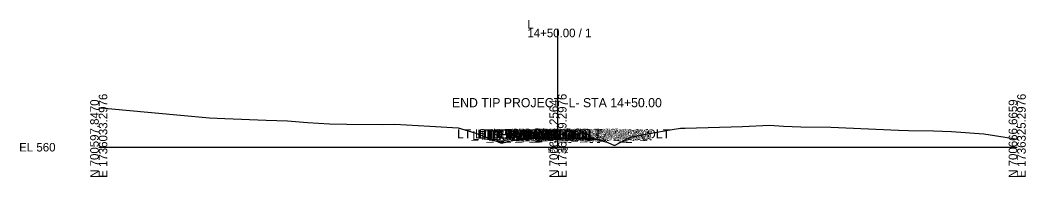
# Model space of a CAD drawing. Extents: x -26 to 697, y -10 to 2642.
# Drawn here: x -25.7 to 302.8, y 2590.3 to 2641.5 of the extents above; entities that cross this region are included whole.
import ezdxf

# ---------------------------------------------------------------- set-up
doc = ezdxf.new("R2010")
doc.units = 0
for name, color, linetype in [('Default', 7, 'Continuous'), ('Exist CMT Pavement', 7, 'Continuous'), ('Exist Cross Section Cell', 7, 'Continuous'), ('Exist XS Center Line Elevation Label', 7, 'Continuous'), ('Exist XS Ground Line', 7, 'Continuous'), ('Prop CMT Pvmt Course 1', 7, 'Continuous'), ('Prop CMT Pvmt Course 1 Wedge', 7, 'Continuous'), ('Prop CMT Pvmt Course 2', 7, 'Continuous'), ('Prop CMT Pvmt Course 2 Wedge', 7, 'Continuous'), ('Prop CMT Pvmt Surface', 7, 'Continuous'), ('Prop CMT Pvmt Surface Shoulder', 7, 'Continuous'), ('Prop CMT Pvmt Wedge Surface 1', 7, 'Continuous'), ('Prop CMT Pvmt Wedge Surface 2', 7, 'Continuous'), ('Prop CMT Shld Paved Course 1', 7, 'Continuous'), ('Prop CMT Shld Paved Course 2', 7, 'Continuous'), ('Prop CMT Slope Grass', 7, 'Continuous'), ('Prop CMT Subgrade Earthwork', 7, 'Continuous'), ('Prop XS SE Text', 7, 'Continuous'), ('Prop XS Side Slope Text', 7, 'Continuous')]:
    doc.layers.add(name, color=color, linetype=linetype)

msp = doc.modelspace()

# ---------------------------------------------------------------- linework, layer by layer
at = {"layer": 'Exist CMT Pavement'}
for points in [[(150, 2603.02), (140.36, 2602.87)], [(140.36, 2602.87), (145.18, 2602.94)], [(145.18, 2602.94), (150, 2603.02)], [(154.82, 2602.95), (150, 2603.02)], [(150, 2603.02), (159.65, 2602.87)], [(159.65, 2602.87), (154.82, 2602.95)]]:
    msp.add_lwpolyline(points, dxfattribs=at)
at = {"layer": 'Exist Cross Section Cell'}
for p, q in [((150, 2600), (150, 2638.72)), ((0, 2600), (150, 2600)), ((150, 2600), (300, 2600))]:
    msp.add_line(p, q, dxfattribs=at)
at = {"layer": 'Exist XS Ground Line'}
msp.add_lwpolyline([(0, 2612.91), (0.83, 2612.84), (8.98, 2612.08), (26.7, 2610.49), (36.16, 2609.64), (41.19, 2609.42), (54.71, 2608.85), (61.69, 2608.57), (68.16, 2608.12), (75.34, 2607.6), (81.04, 2607.57), (92.53, 2607.38), (96.74, 2607.49), (108.14, 2606.89), (117.37, 2606.36), (122.81, 2604.68), (131.51, 2601.35), (136.08, 2602.43), (140.32, 2602.87), (147.42, 2602.97), (149.92, 2603.02), (152.45, 2602.99), (159.65, 2602.87), (160.58, 2602.74), (163.68, 2602.33), (166.32, 2601.5), (168.44, 2600.51), (171.97, 2602.4), (173.71, 2603.3), (179.74, 2604.43), (187.34, 2605.75), (189.97, 2606.2), (191.5, 2606.25), (210.28, 2606.73), (219.14, 2607.15), (223.68, 2606.87), (229.3, 2606.65), (239.08, 2606.6), (261.25, 2605.54), (264.53, 2605.47), (272.61, 2605.38), (278.5, 2605.11), (289.13, 2604.41), (296.1, 2603.33), (300, 2602.59)], dxfattribs=at)
at = {"layer": 'Prop CMT Pvmt Course 1'}
for points in [[(150, 2603.12), (140.36, 2602.99)], [(140.36, 2602.88), (150, 2603.02)], [(140.36, 2602.99), (140.36, 2602.78), (140.36, 2602.78), (140.36, 2602.88)], [(150, 2602.92), (150, 2603.12)], [(150, 2603.12), (159.65, 2602.96)], [(150, 2602.92), (150, 2603.12)], [(150, 2603.02), (150, 2602.92), (150, 2602.92)], [(159.65, 2602.86), (150, 2603.02)], [(150, 2603.02), (150, 2602.92), (150, 2602.92)], [(159.65, 2602.96), (159.65, 2602.75)], [(159.65, 2602.75), (159.65, 2602.86)], [(159.65, 2602.75), (159.65, 2602.75)]]:
    msp.add_lwpolyline(points, dxfattribs=at)
at = {"layer": 'Prop CMT Pvmt Course 1 Wedge'}
for points in [[(150, 2603.02), (140.36, 2602.88)], [(150, 2603.02), (159.65, 2602.86)]]:
    msp.add_lwpolyline(points, dxfattribs=at)
at = {"layer": 'Prop CMT Pvmt Course 2'}
for points in [[(140.36, 2602.32), (140.36, 2602.32), (140.36, 2602.78), (140.36, 2602.78)], [(140.36, 2602.78), (140.36, 2602.32)], [(159.65, 2602.29), (159.65, 2602.75)], [(159.65, 2602.75), (159.65, 2602.75)], [(159.65, 2602.75), (159.65, 2602.29)], [(159.65, 2602.29), (159.65, 2602.29)]]:
    msp.add_lwpolyline(points, dxfattribs=at)
at = {"layer": 'Prop CMT Pvmt Course 2 Wedge'}
for points in [[(150, 2602.92), (140.36, 2602.78)], [(150, 2602.92), (159.65, 2602.75)]]:
    msp.add_lwpolyline(points, dxfattribs=at)
at = {"layer": 'Prop CMT Pvmt Surface'}
for points in [[(150, 2603.12), (140.36, 2602.99)], [(150, 2603.12), (159.65, 2602.96)]]:
    msp.add_lwpolyline(points, dxfattribs=at)
at = {"layer": 'Prop CMT Pvmt Surface Shoulder'}
for points in [[(140.36, 2602.99), (140.35, 2602.99)], [(159.65, 2602.96), (159.66, 2602.96)]]:
    msp.add_lwpolyline(points, dxfattribs=at)
at = {"layer": 'Prop CMT Pvmt Wedge Surface 1'}
for points in [[(150, 2603.02), (140.36, 2602.88)], [(140.36, 2602.78), (140.36, 2602.99)], [(140.36, 2602.88), (140.36, 2602.78), (140.36, 2602.78)], [(150, 2603.12), (150, 2602.92), (150, 2602.92), (150, 2603.02)], [(150, 2603.12), (150, 2602.92), (150, 2602.92), (150, 2603.02)], [(150, 2603.02), (159.65, 2602.86)], [(159.65, 2602.75), (159.65, 2602.96)], [(159.65, 2602.86), (159.65, 2602.75)], [(159.65, 2602.75), (159.65, 2602.75)]]:
    msp.add_lwpolyline(points, dxfattribs=at)
at = {"layer": 'Prop CMT Pvmt Wedge Surface 2'}
for points in [[(140.36, 2602.78), (140.36, 2602.99)], [(150, 2602.92), (140.36, 2602.78)], [(150, 2603.12), (150, 2602.92)], [(150, 2603.12), (150, 2602.92)], [(150, 2602.92), (159.65, 2602.75)], [(159.65, 2602.75), (159.65, 2602.96)]]:
    msp.add_lwpolyline(points, dxfattribs=at)
at = {"layer": 'Prop CMT Shld Paved Course 1'}
for points in [[(140.36, 2602.99), (140.35, 2602.99), (140.14, 2602.77)], [(140.14, 2602.77), (140.36, 2602.78)], [(140.36, 2602.78), (140.36, 2602.99)], [(159.65, 2602.96), (159.66, 2602.96), (159.87, 2602.75)], [(159.65, 2602.75), (159.65, 2602.96)], [(159.87, 2602.75), (159.65, 2602.75)]]:
    msp.add_lwpolyline(points, dxfattribs=at)
at = {"layer": 'Prop CMT Shld Paved Course 2'}
for points in [[(140.36, 2602.78), (140.14, 2602.77), (140.13, 2602.77), (139.66, 2602.31)], [(139.66, 2602.31), (140.36, 2602.32)], [(140.36, 2602.32), (140.36, 2602.78)], [(159.65, 2602.75), (159.87, 2602.75), (159.88, 2602.75), (160.35, 2602.28)], [(159.65, 2602.29), (159.65, 2602.75)], [(160.35, 2602.28), (159.65, 2602.29)]]:
    msp.add_lwpolyline(points, dxfattribs=at)
at = {"layer": 'Prop CMT Slope Grass'}
for points in [[(140.35, 2602.99), (137.27, 2602.76), (136.74, 2602.49)], [(159.66, 2602.96), (162.72, 2602.72), (163.45, 2602.36)]]:
    msp.add_lwpolyline(points, dxfattribs=at)
at = {"layer": 'Prop CMT Subgrade Earthwork'}
for points in [[(139.66, 2602.31), (139.08, 2602.89)], [(140.36, 2602.32), (139.66, 2602.31)], [(140.36, 2602.32), (140.37, 2602.87)], [(140.36, 2602.32), (140.36, 2602.32)], [(159.65, 2602.29), (159.63, 2602.87)], [(159.65, 2602.29), (159.65, 2602.29)], [(159.65, 2602.29), (160.35, 2602.28)], [(160.35, 2602.28), (160.93, 2602.86)]]:
    msp.add_lwpolyline(points, dxfattribs=at)

# ---------------------------------------------------------------- texts
at = {"layer": 'Default'}
for s, height, p in [('LT_Sub_Trench_Out_DLT', 3, (117.03, 2602.89)), ('LT_Sub_Trench_Out', 3, (121.99, 2602.31)), ('LT_PV_Sub_Tie_Out', 3, (122.87, 2602.87)), ('LT_GS_OS_CTL', 3, (123.67, 2602.76)), ('LT_PS2_Shelf_Out', 3, (124.1, 2602.77)), ('LT_PV_OEEOP_EG', 3, (124.15, 2602.87)), ('LT_Slope_Fill', 3, (125.46, 2602.49)), ('LT_PV2_OEEOP', 3, (126.54, 2602.78)), ('LT_Sub_OEEOP', 3, (126.61, 2602.32)), ('LT_PV1_OEEOP', 3, (126.9, 2602.88)), ('LT_PS2_OEOP', 3, (127.5, 2602.77)), ('LT_PV2_OEOT', 3, (127.6, 2602.78)), ('LT_Sub_OEOT', 3, (127.67, 2602.32)), ('LT_PV1_OEOT', 3, (127.96, 2602.99)), ('LT_PS1_OEOP', 3, (128.07, 2602.99)), ('LT_PV_EG_TestPt', 3, (130.3, 2602.94)), ('RT_PV_IEEOP_EG', 3, (134.76, 2603.02)), ('LT_PV_IEEOP_EG', 3, (134.93, 2603.02)), ('RT_PV2_IEEOP', 3, (137.14, 2602.92)), ('LT_PV2_IEEOP', 3, (137.32, 2602.92)), ('RT_PV1_IEEOP', 3, (137.5, 2603.02)), ('LT_PV1_IEEOP', 3, (137.68, 2603.02)), ('RT_Sub_Trench_Out_DLT', 3, (138.7, 2602.86)), ('RT_PV_EG_TestPt', 3, (139.77, 2602.95)), ('RT_PV_Sub_Tie_Out', 3, (141.95, 2602.87)), ('PV2_PGL', 3, (142.05, 2602.92)), ('PV1_PGL', 3, (142.41, 2603.12)), ('RT_Sub_Trench_Out', 3, (142.5, 2602.28)), ('RT_PV_OEEOP_EG', 3, (143.26, 2602.87)), ('RT_PS2_Shelf_Out', 3, (143.67, 2602.75)), ('RT_PV2_OEEOP', 3, (145.65, 2602.75)), ('RT_Sub_OEEOP', 3, (145.72, 2602.29)), ('RT_PV1_OEEOP', 3, (146.01, 2602.86)), ('RT_PV2_OEOT', 3, (146.71, 2602.75)), ('RT_Sub_OEOT', 3, (146.78, 2602.29)), ('RT_PS2_OEOP', 3, (147.05, 2602.75)), ('RT_PV1_OEOT', 3, (147.07, 2602.96)), ('RT_PS1_OEOP', 3, (147.2, 2602.96)), ('RT_GS_OS_CTL', 3, (148.93, 2602.72)), ('RT_Slope_Fill', 3, (151.99, 2602.36)), ('-', 0.0001, (0, 2600))]:
    msp.add_text(s, height=height, dxfattribs=at).set_placement(p)
at = {"layer": 'Exist Cross Section Cell'}
for s, p in [('L', (140, 2638.72)), ('14+50.00 / 1', (140, 2635.92)), ('EL 560', (-26, 2598.6))]:
    msp.add_text(s, height=2.8, dxfattribs=at).set_placement(p)
for s, p in [('N 700597.8470', (0, 2590)), ('E 1736033.2976', (2.8, 2590)), ('N 700632.2564', (150, 2590)), ('E 1736179.2976', (152.8, 2590)), ('N 700666.6659', (300, 2590)), ('E 1736325.2976', (302.8, 2590))]:
    msp.add_text(s, height=2.8, rotation=90, dxfattribs=at).set_placement(p)
at = {"layer": 'Exist XS Center Line Elevation Label'}
msp.add_text('563.02', height=1.6, dxfattribs=at).set_placement((146.63, 2598.22))
at = {"layer": 'Prop XS SE Text'}
for rotation, p in [(1.1458, (140.61, 2603.96)), (358.8542, (151.65, 2604.1))]:
    msp.add_text('EXIST.', height=2, rotation=rotation, dxfattribs=at).set_placement(p)
at = {"layer": 'Prop XS Side Slope Text'}
msp.add_text('END TIP PROJECT -L- STA 14+50.00', height=3, dxfattribs=at).set_placement((115.37, 2613.05))
for rotation, p in [(26.5651, (135.25, 2602.58)), (333.4349, (161.99, 2603.92))]:
    msp.add_text('2:1', height=2, rotation=rotation, dxfattribs=at).set_placement(p)

doc.saveas('drawing.dxf')
